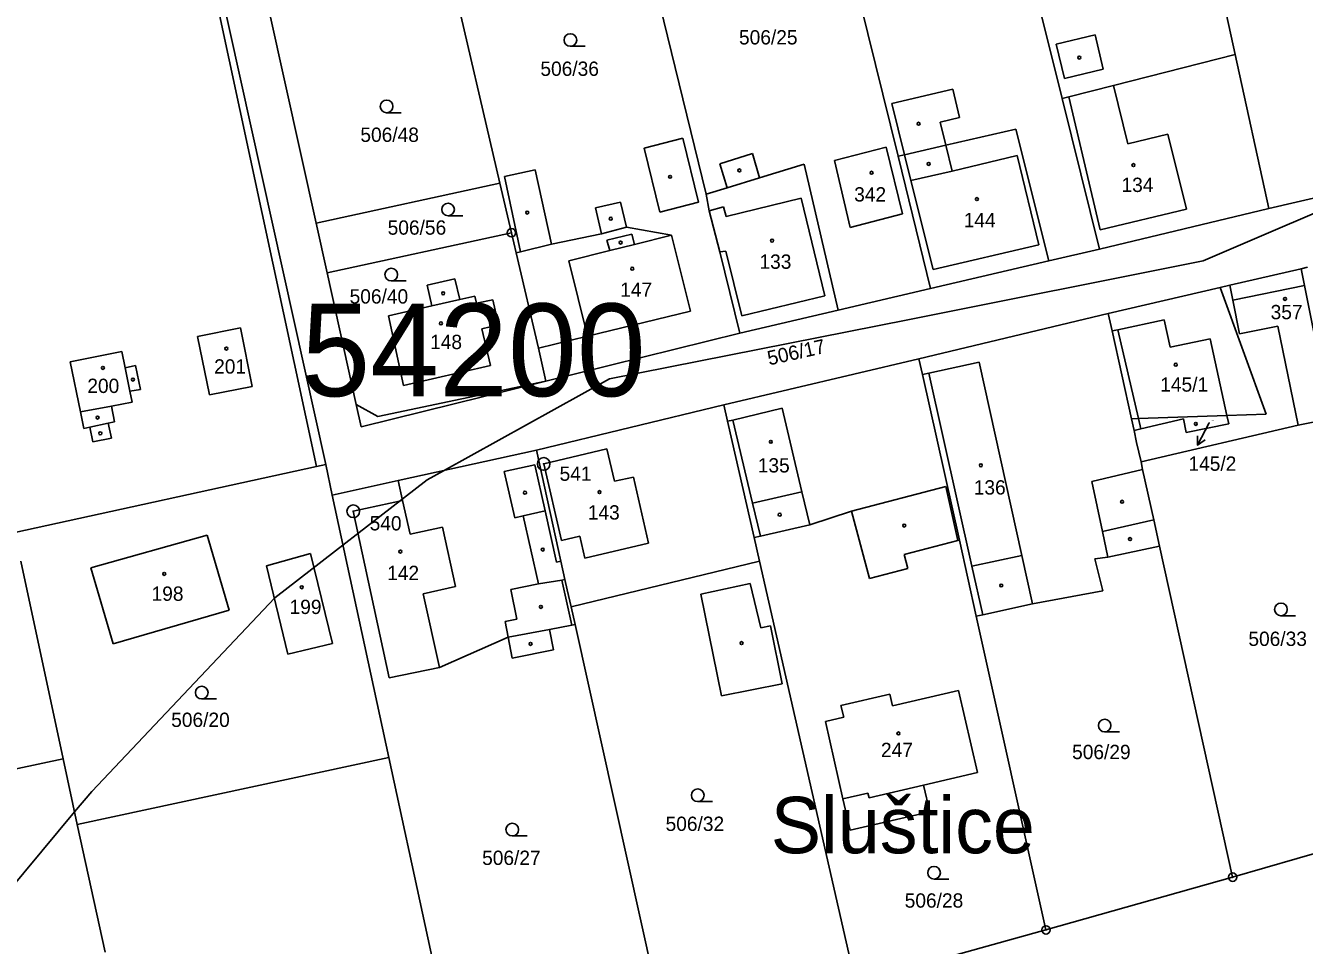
# Model space of a CAD drawing. Extents: x -725765 to -723182, y -1052705 to -1049154.
# Drawn here: x -724986 to -724834.1, y -1051317.3 to -1051208.1 of the extents above; entities that cross this region are included whole.
import ezdxf

# ---------------------------------------------------------------- set-up
doc = ezdxf.new("R2010")
doc.units = 0
for name, color, linetype in [('Vrstva 1', 7, 'Continuous'), ('Vrstva 15', 7, 'Continuous'), ('Vrstva 16', 7, 'Continuous'), ('Vrstva 17', 7, 'Continuous'), ('Vrstva 18', 7, 'Continuous'), ('Vrstva 19', 7, 'Continuous'), ('Vrstva 25', 7, 'Continuous'), ('Vrstva 4', 7, 'Continuous'), ('Vrstva 52', 7, 'Continuous'), ('Vrstva 53', 7, 'Continuous')]:
    doc.layers.add(name, color=color, linetype=linetype)

msp = doc.modelspace()

# ---------------------------------------------------------------- linework, layer by layer
at = {"layer": 'Vrstva 1'}
for points in [[(-724973.12, -1051157.17), (-724950.33, -1051260.17)], [(-724849.09, -1051180.48), (-724842.32, -1051211.51)], [(-724870.61, -1051185.73), (-724862.89, -1051216.71)], [(-724890.47, -1051190.71), (-724882.37, -1051223.57)], [(-724912.94, -1051196.18), (-724905.17, -1051228.09)], [(-724929.66, -1051226.78), (-724935.5, -1051201.73)], [(-724951.47, -1051231.54), (-724956.97, -1051206.71)], [(-724856.77, -1051215.16), (-724842.32, -1051211.51)], [(-724842.32, -1051211.51), (-724838.34, -1051229.79)], [(-724862.89, -1051216.71), (-724862.08, -1051216.5)], [(-724862.08, -1051216.5), (-724856.77, -1051215.16)], [(-724862.89, -1051216.71), (-724858.44, -1051234.59)], [(-724876.69, -1051222.27), (-724868.37, -1051220.37)], [(-724868.37, -1051220.37), (-724864.48, -1051236.01)], [(-724889.93, -1051224.09), (-724883.8, -1051222.5)], [(-724883.8, -1051222.5), (-724881.86, -1051230.43)], [(-724881.6, -1051223.39), (-724876.69, -1051222.27)], [(-724903.53, -1051224.49), (-724899.64, -1051223.26)], [(-724899.64, -1051223.26), (-724898.81, -1051226.13)], [(-724889.93, -1051224.09), (-724888.05, -1051232.02)], [(-724882.37, -1051223.57), (-724881.6, -1051223.39)], [(-724882.37, -1051223.57), (-724878.5, -1051239.3)], [(-724903.53, -1051224.49), (-724902.66, -1051227.32)], [(-724898.81, -1051226.13), (-724893.53, -1051224.5)], [(-724893.53, -1051224.5), (-724889.47, -1051241.86)], [(-724951.47, -1051231.54), (-724929.66, -1051226.78)], [(-724928.29, -1051232.66), (-724929.66, -1051226.78)], [(-724838.34, -1051229.79), (-724823.81, -1051226.41)], [(-724905.17, -1051228.09), (-724902.66, -1051227.32)], [(-724905.17, -1051228.09), (-724904.82, -1051230.05)], [(-724918.29, -1051229.71), (-724915.34, -1051229.02)], [(-724918.29, -1051229.71), (-724917.59, -1051232.77)], [(-724915.34, -1051229.02), (-724914.64, -1051232)], [(-724904.82, -1051230.05), (-724903.55, -1051234.94)], [(-724858.44, -1051234.59), (-724838.34, -1051229.79)], [(-724950.17, -1051237.43), (-724951.47, -1051231.54)], [(-724888.05, -1051232.02), (-724881.86, -1051230.43)], [(-724950.17, -1051237.43), (-724928.29, -1051232.66)], [(-724928.29, -1051232.66), (-724927.74, -1051235.04)], [(-724923.54, -1051234.03), (-724917.59, -1051232.77)], [(-724914.64, -1051232), (-724909.29, -1051232.93)], [(-724909.29, -1051232.93), (-724907.01, -1051241.97)], [(-724927.23, -1051234.92), (-724923.54, -1051234.03)], [(-724864.48, -1051236.01), (-724858.44, -1051234.59)], [(-724927.74, -1051235.04), (-724927.23, -1051234.92)], [(-724927.74, -1051235.04), (-724925.09, -1051246.38)], [(-724903.55, -1051234.94), (-724901.15, -1051244.59)], [(-724878.5, -1051239.3), (-724864.48, -1051236.01)], [(-724950.17, -1051237.43), (-724946.73, -1051253.05)], [(-724842.95, -1051238.88), (-724834.51, -1051236.93)], [(-724834.51, -1051236.93), (-724833.73, -1051236.75)], [(-724938.31, -1051238.87), (-724935.01, -1051238.12)], [(-724938.31, -1051238.87), (-724937.75, -1051241.35)], [(-724935.01, -1051238.12), (-724934.41, -1051240.6)], [(-724889.47, -1051241.86), (-724878.5, -1051239.3)], [(-724857.41, -1051242.23), (-724844.11, -1051239.15)], [(-724844.11, -1051239.15), (-724842.95, -1051238.88)], [(-724844.11, -1051239.15), (-724838.63, -1051254.19)], [(-724842.6, -1051240.67), (-724834.11, -1051238.93)], [(-724834.11, -1051238.93), (-724830.91, -1051254.72)], [(-724934.41, -1051240.6), (-724932.62, -1051240.19)], [(-724932.62, -1051240.19), (-724932.43, -1051241.04)], [(-724932.43, -1051241.04), (-724930.5, -1051240.61)], [(-724930.5, -1051240.61), (-724929.83, -1051243.59)], [(-724842.6, -1051240.67), (-724841.81, -1051244.68)], [(-724942.89, -1051242.52), (-724937.75, -1051241.35)], [(-724919.26, -1051244.96), (-724907.01, -1051241.97)], [(-724901.15, -1051244.59), (-724889.47, -1051241.86)], [(-724879.9, -1051247.64), (-724857.41, -1051242.23)], [(-724857.41, -1051242.23), (-724856.95, -1051244.32)], [(-724942.89, -1051242.52), (-724941.09, -1051250.79)], [(-724931.79, -1051244.06), (-724929.83, -1051243.59)], [(-724841.81, -1051244.68), (-724837.28, -1051243.75)], [(-724837.28, -1051243.75), (-724834.86, -1051255.5)], [(-724965.56, -1051244.97), (-724960.47, -1051243.94)], [(-724965.56, -1051244.97), (-724964.15, -1051251.92)], [(-724960.47, -1051243.94), (-724959.08, -1051250.93)], [(-724931.79, -1051244.06), (-724930.79, -1051248.41)], [(-724925.09, -1051246.38), (-724919.26, -1051244.96)], [(-724924.19, -1051250.27), (-724901.15, -1051244.59)], [(-724856.95, -1051244.32), (-724854.64, -1051254.76)], [(-724980.68, -1051247.97), (-724974.58, -1051246.75)], [(-724974.58, -1051246.75), (-724974.17, -1051248.71)], [(-724925.09, -1051246.38), (-724924.19, -1051250.27)], [(-724980.68, -1051247.97), (-724979.48, -1051253.94)], [(-724941.09, -1051250.79), (-724930.79, -1051248.41)], [(-724903.06, -1051253.09), (-724879.9, -1051247.64)], [(-724879.9, -1051247.64), (-724879.45, -1051249.51)], [(-724974.17, -1051248.71), (-724972.93, -1051248.44)], [(-724972.93, -1051248.44), (-724972.35, -1051251.27)], [(-724879.45, -1051249.51), (-724875.09, -1051269.17)], [(-724973.6, -1051251.47), (-724972.35, -1051251.27)], [(-724964.15, -1051251.92), (-724959.08, -1051250.93)], [(-724946.15, -1051255.69), (-724924.19, -1051250.27)], [(-724975.8, -1051253.25), (-724973.33, -1051252.78)], [(-724973.6, -1051251.47), (-724973.33, -1051252.78)], [(-724979.48, -1051253.94), (-724979.09, -1051255.9)], [(-724975.8, -1051253.25), (-724975.43, -1051255.13)], [(-724946.73, -1051253.05), (-724946.15, -1051255.69)], [(-724925.3, -1051258.49), (-724903.06, -1051253.09)], [(-724903.06, -1051253.09), (-724902.62, -1051255.04)], [(-724853.82, -1051254.73), (-724843.31, -1051254.36)], [(-724843.31, -1051254.36), (-724838.63, -1051254.19)], [(-724843.31, -1051254.36), (-724843.09, -1051255.35)], [(-724979.09, -1051255.9), (-724978.35, -1051255.75)], [(-724978.35, -1051255.75), (-724977.99, -1051257.49)], [(-724976.2, -1051255.29), (-724975.43, -1051255.13)], [(-724976.2, -1051255.29), (-724975.78, -1051257.06)], [(-724902.62, -1051255.04), (-724899.47, -1051268.86)], [(-724854.64, -1051254.76), (-724853.82, -1051254.73)], [(-724854.64, -1051254.76), (-724854.34, -1051256.14)], [(-724853.82, -1051254.73), (-724853.54, -1051255.95)], [(-724853.54, -1051255.95), (-724848.46, -1051254.77)], [(-724848.46, -1051254.77), (-724848.14, -1051256.37)], [(-724848.14, -1051256.37), (-724843.09, -1051255.35)], [(-724834.86, -1051255.5), (-724830.91, -1051254.72)], [(-724977.99, -1051257.49), (-724975.78, -1051257.06)], [(-724854.34, -1051256.14), (-724854.03, -1051257.56)], [(-724941.73, -1051262.1), (-724925.3, -1051258.49)], [(-724925.3, -1051258.49), (-724922.43, -1051271.66)], [(-724854.03, -1051257.56), (-724853.51, -1051259.87)], [(-724987.27, -1051268.24), (-724951.45, -1051260.42)], [(-724951.45, -1051260.42), (-724950.33, -1051260.17)], [(-724950.33, -1051260.17), (-724949.59, -1051263.83)], [(-724853.51, -1051259.87), (-724853.32, -1051260.77)], [(-724853.32, -1051260.77), (-724852, -1051266.76)], [(-724949.59, -1051263.83), (-724941.73, -1051262.1)], [(-724941.73, -1051262.1), (-724941.21, -1051264.44)], [(-724949.59, -1051263.83), (-724942.84, -1051294.98)], [(-724947.08, -1051265.73), (-724941.21, -1051264.44)], [(-724947.08, -1051265.73), (-724942.8, -1051285.51)], [(-724892.83, -1051267.33), (-724887.9, -1051265.73)], [(-724887.9, -1051265.73), (-724885.76, -1051273.72)], [(-724898.72, -1051268.69), (-724892.83, -1051267.33)], [(-724852, -1051266.76), (-724851.31, -1051269.88)], [(-724978.23, -1051272.46), (-724964.44, -1051268.56)], [(-724964.44, -1051268.56), (-724961.82, -1051277.49)], [(-724899.47, -1051268.86), (-724898.72, -1051268.69)], [(-724899.47, -1051268.86), (-724898.83, -1051271.67)], [(-724881.65, -1051270.87), (-724875.25, -1051269.21)], [(-724875.25, -1051269.21), (-724875.09, -1051269.17)], [(-724875.09, -1051269.17), (-724873.08, -1051278.19)], [(-724957.39, -1051272.21), (-724952.16, -1051270.77)], [(-724952.16, -1051270.77), (-724949.53, -1051281.43)], [(-724881.65, -1051270.87), (-724881.21, -1051272.55)], [(-724859.01, -1051271.39), (-724857.44, -1051271.18)], [(-724857.44, -1051271.18), (-724851.31, -1051269.88)], [(-724851.31, -1051269.88), (-724842.63, -1051309.19)], [(-724986.54, -1051271.66), (-724981.52, -1051295.13)], [(-724978.23, -1051272.46), (-724975.58, -1051281.47)], [(-724957.39, -1051272.21), (-724954.83, -1051282.72)], [(-724922.43, -1051271.66), (-724921.95, -1051273.85)], [(-724921.18, -1051277.09), (-724898.83, -1051271.67)], [(-724898.83, -1051271.67), (-724887.44, -1051321.75)], [(-724885.76, -1051273.72), (-724881.21, -1051272.55)], [(-724859.01, -1051271.39), (-724858.06, -1051275.2)], [(-724921.95, -1051273.85), (-724921.68, -1051275.08)], [(-724921.68, -1051275.08), (-724921.18, -1051277.09)], [(-724866.41, -1051276.72), (-724858.06, -1051275.2)], [(-724921.18, -1051277.09), (-724920.71, -1051279.19)], [(-724872.3, -1051278.02), (-724866.41, -1051276.72)], [(-724975.58, -1051281.47), (-724961.82, -1051277.49)], [(-724873.08, -1051278.19), (-724872.3, -1051278.02)], [(-724873.08, -1051278.19), (-724864.8, -1051315.46)], [(-724928.67, -1051280.7), (-724923.77, -1051279.79)], [(-724923.77, -1051279.79), (-724921.11, -1051279.27)], [(-724921.11, -1051279.27), (-724920.71, -1051279.19)], [(-724920.71, -1051279.19), (-724909.84, -1051328.29)], [(-724954.83, -1051282.72), (-724949.53, -1051281.43)], [(-724936.83, -1051284.28), (-724928.67, -1051280.7)], [(-724942.8, -1051285.51), (-724936.83, -1051284.28)], [(-724889.15, -1051288.79), (-724883.34, -1051287.46)], [(-724883.34, -1051287.46), (-724883.02, -1051288.86)], [(-724883.02, -1051288.86), (-724875.19, -1051287.04)], [(-724875.19, -1051287.04), (-724872.93, -1051296.76)], [(-724889.15, -1051288.79), (-724888.81, -1051290.2)], [(-724890.99, -1051290.71), (-724888.81, -1051290.2)], [(-724890.99, -1051290.71), (-724888.91, -1051299.9)], [(-725024.07, -1051304.22), (-724981.52, -1051295.13)], [(-724981.52, -1051295.13), (-724979.85, -1051302.94)], [(-724979.85, -1051302.94), (-724942.84, -1051294.98)], [(-724942.84, -1051294.98), (-724934.23, -1051334.87)], [(-724879.34, -1051298.26), (-724872.93, -1051296.76)], [(-724879.34, -1051298.26), (-724878.59, -1051301.45)], [(-724888.91, -1051299.9), (-724888.07, -1051303.62)], [(-724888.07, -1051303.62), (-724878.59, -1051301.45)], [(-724979.85, -1051302.94), (-724976.54, -1051318.1)], [(-724842.63, -1051309.19), (-724819.59, -1051302.54)], [(-724864.8, -1051315.46), (-724842.63, -1051309.19)], [(-724887.44, -1051321.75), (-724864.8, -1051315.46)]]:
    msp.add_lwpolyline(points, dxfattribs=at)
at = {"layer": 'Vrstva 16'}
msp.add_lwpolyline([(-724845.39, -1051255.22), (-724845.4, -1051255.24)], dxfattribs=at)
at = {"layer": 'Vrstva 25'}
for points in [[(-724921.29, -1051210.52), (-724919.54, -1051210.52)], [(-724943.12, -1051218.41), (-724941.37, -1051218.41)], [(-724935.82, -1051230.65), (-724934.07, -1051230.65)], [(-724942.56, -1051238.38), (-724940.81, -1051238.38)], [(-724845.4, -1051255.24), (-724846.82, -1051257.88)], [(-724845.91, -1051257.24), (-724846.82, -1051257.88), (-724846.79, -1051256.76)], [(-724836.9, -1051278.14), (-724835.15, -1051278.14)], [(-724965.07, -1051288.02), (-724963.32, -1051288.02)], [(-724857.83, -1051291.93), (-724856.08, -1051291.93)], [(-724906.16, -1051300.21), (-724904.41, -1051300.21)], [(-724928.19, -1051304.29), (-724926.44, -1051304.29)], [(-724878.09, -1051309.42), (-724876.34, -1051309.42)]]:
    msp.add_lwpolyline(points, dxfattribs=at)
for centre, radius in [((-724921.29, -1051209.77), 0.75), ((-724860.84, -1051211.86), 0.175), ((-724943.12, -1051217.66), 0.75), ((-724879.93, -1051219.72), 0.175), ((-724901.22, -1051225.26), 0.175), ((-724885.52, -1051225.54), 0.175), ((-724878.73, -1051224.48), 0.175), ((-724854.41, -1051224.62), 0.175), ((-724909.45, -1051226.02), 0.175), ((-724873, -1051228.66), 0.175), ((-724935.82, -1051229.9), 0.75), ((-724926.41, -1051230.26), 0.175), ((-724916.49, -1051230.99), 0.175), ((-724928.29, -1051232.66), 0.5), ((-724928.29, -1051232.66), 0.032), ((-724915.32, -1051233.83), 0.175), ((-724897.33, -1051233.6), 0.175), ((-724942.56, -1051237.63), 0.75), ((-724913.94, -1051236.93), 0.175), ((-724936.4, -1051239.85), 0.175), ((-724836.41, -1051240.52), 0.175), ((-724936.66, -1051243.42), 0.175), ((-724962.15, -1051246.41), 0.175), ((-724849.39, -1051248.33), 0.175), ((-724976.81, -1051248.71), 0.175), ((-724973.25, -1051250.1), 0.175), ((-724977.44, -1051254.61), 0.175), ((-724847, -1051255.36), 0.175), ((-724977.12, -1051256.48), 0.175), ((-724897.48, -1051257.49), 0.175), ((-724924.46, -1051260.11), 0.75), ((-724924.46, -1051260.11), 0.032), ((-724872.54, -1051260.28), 0.175), ((-724926.68, -1051263.53), 0.175), ((-724917.83, -1051263.46), 0.175), ((-724947.08, -1051265.73), 0.75), ((-724855.76, -1051264.61), 0.175), ((-724947.08, -1051265.73), 0.032), ((-724896.43, -1051266.14), 0.175), ((-724881.64, -1051267.44), 0.175), ((-724854.82, -1051269.04), 0.175), ((-724941.48, -1051270.52), 0.175), ((-724924.57, -1051270.28), 0.175), ((-724969.52, -1051273.17), 0.175), ((-724953.19, -1051274.76), 0.175), ((-724870.11, -1051274.55), 0.175), ((-724924.79, -1051277.09), 0.175), ((-724836.9, -1051277.39), 0.75), ((-724926.02, -1051281.49), 0.175), ((-724900.96, -1051281.39), 0.175), ((-724965.07, -1051287.27), 0.75), ((-724857.83, -1051291.18), 0.75), ((-724882.32, -1051292.12), 0.175), ((-724906.16, -1051299.46), 0.75), ((-724928.19, -1051303.54), 0.75), ((-724878.09, -1051308.67), 0.75), ((-724842.63, -1051309.19), 0.5), ((-724842.63, -1051309.19), 0.032), ((-724864.8, -1051315.46), 0.5), ((-724864.8, -1051315.46), 0.032)]:
    msp.add_circle(centre, radius, dxfattribs=at)
at = {"layer": 'Vrstva 4'}
for points in [[(-724973.59, -1051157.32), (-724951.45, -1051260.42)], [(-724863.59, -1051210.27), (-724858.97, -1051209.17)], [(-724863.59, -1051210.27), (-724862.62, -1051214.34)], [(-724858.97, -1051209.17), (-724858, -1051213.24)], [(-724862.62, -1051214.34), (-724858, -1051213.24)], [(-724883.1, -1051217.33), (-724875.88, -1051215.6)], [(-724875.88, -1051215.6), (-724875.07, -1051218.97)], [(-724862.08, -1051216.5), (-724858.35, -1051232.31)], [(-724856.77, -1051215.16), (-724855.07, -1051222.12)], [(-724883.1, -1051217.33), (-724881.6, -1051223.39)], [(-724877.36, -1051219.54), (-724875.07, -1051218.97)], [(-724877.36, -1051219.54), (-724876.69, -1051222.27)], [(-724855.07, -1051222.12), (-724850.31, -1051220.94)], [(-724850.31, -1051220.94), (-724848.1, -1051229.85)], [(-724912.53, -1051222.63), (-724907.92, -1051221.43)], [(-724907.92, -1051221.43), (-724906.06, -1051229.01)], [(-724876.69, -1051222.27), (-724875.93, -1051225.35)], [(-724912.53, -1051222.63), (-724910.68, -1051230.22)], [(-724881.6, -1051223.39), (-724880.84, -1051226.45)], [(-724875.93, -1051225.35), (-724868.22, -1051223.49)], [(-724868.22, -1051223.49), (-724865.66, -1051234.08)], [(-724929.13, -1051225.97), (-724925.47, -1051225.17)], [(-724925.47, -1051225.17), (-724923.54, -1051234.03)], [(-724880.84, -1051226.45), (-724875.93, -1051225.35)], [(-724929.13, -1051225.97), (-724927.23, -1051234.92)], [(-724902.66, -1051227.32), (-724898.81, -1051226.13)], [(-724880.84, -1051226.45), (-724878.21, -1051237.03)], [(-724902.8, -1051230.73), (-724893.88, -1051228.57)], [(-724893.88, -1051228.57), (-724891.08, -1051240.14)], [(-724910.68, -1051230.22), (-724906.06, -1051229.01)], [(-724904.82, -1051230.05), (-724903.1, -1051229.57)], [(-724903.1, -1051229.57), (-724902.8, -1051230.73)], [(-724858.35, -1051232.31), (-724848.1, -1051229.85)], [(-724917.59, -1051232.77), (-724914.64, -1051232)], [(-724916.94, -1051233.55), (-724914, -1051232.81)], [(-724914, -1051232.81), (-724913.69, -1051234.04)], [(-724913.69, -1051234.04), (-724909.29, -1051232.93)], [(-724916.94, -1051233.55), (-724916.61, -1051234.77)], [(-724916.61, -1051234.77), (-724913.69, -1051234.04)], [(-724878.21, -1051237.03), (-724865.66, -1051234.08)], [(-724921.48, -1051236), (-724916.61, -1051234.77)], [(-724921.48, -1051236), (-724919.26, -1051244.96)], [(-724903.55, -1051234.94), (-724902.83, -1051234.84)], [(-724902.83, -1051234.84), (-724900.91, -1051242.51)], [(-724834.51, -1051236.93), (-724834.11, -1051238.93)], [(-724842.95, -1051238.88), (-724842.6, -1051240.67)], [(-724937.75, -1051241.35), (-724934.41, -1051240.6)], [(-724900.91, -1051242.51), (-724891.08, -1051240.14)], [(-724856.27, -1051244.18), (-724850.77, -1051243.01)], [(-724850.77, -1051243.01), (-724850.06, -1051246.23)], [(-724856.95, -1051244.32), (-724856.27, -1051244.18)], [(-724856.27, -1051244.18), (-724853.82, -1051254.73)], [(-724850.06, -1051246.23), (-724845.31, -1051245.26)], [(-724845.31, -1051245.26), (-724843.31, -1051254.36)], [(-724878.72, -1051249.35), (-724872.74, -1051248.01)], [(-724872.74, -1051248.01), (-724867.67, -1051270.99)], [(-724974.17, -1051248.71), (-724973.6, -1051251.47)], [(-724879.45, -1051249.51), (-724878.72, -1051249.35)], [(-724878.72, -1051249.35), (-724873.59, -1051272.27)], [(-724944.15, -1051254.48), (-724924.19, -1051250.27)], [(-724979.48, -1051253.94), (-724975.8, -1051253.25)], [(-724946.73, -1051253.05), (-724944.15, -1051254.48)], [(-724902.01, -1051254.9), (-724896.12, -1051253.5)], [(-724896.12, -1051253.5), (-724893.78, -1051263.41)], [(-724978.35, -1051255.75), (-724976.2, -1051255.29)], [(-724902.62, -1051255.04), (-724902.01, -1051254.9)], [(-724902.01, -1051254.9), (-724899.66, -1051264.76)], [(-724854.34, -1051256.14), (-724853.54, -1051255.95)], [(-724853.51, -1051259.87), (-724834.86, -1051255.5)], [(-724924.46, -1051260.11), (-724916.96, -1051258.32)], [(-724916.96, -1051258.32), (-724916.04, -1051262.16)], [(-724929.15, -1051261), (-724925.5, -1051260.24)], [(-724925.5, -1051260.24), (-724924.28, -1051265.69)], [(-724924.46, -1051260.11), (-724922.35, -1051269.19)], [(-724929.15, -1051261), (-724927.9, -1051266.51)], [(-724916.04, -1051262.16), (-724913.81, -1051261.7)], [(-724913.81, -1051261.7), (-724912, -1051269.54)], [(-724859.36, -1051262.2), (-724853.32, -1051260.77)], [(-724899.66, -1051264.76), (-724893.78, -1051263.41)], [(-724893.78, -1051263.41), (-724892.83, -1051267.33)], [(-724887.9, -1051265.73), (-724876.7, -1051262.79)], [(-724876.7, -1051262.79), (-724875.25, -1051269.21)], [(-724859.36, -1051262.2), (-724858.09, -1051268.14)], [(-724941.21, -1051264.44), (-724940.31, -1051268.46)], [(-724899.66, -1051264.76), (-724898.72, -1051268.69)], [(-724927.9, -1051266.51), (-724926.89, -1051266.28)], [(-724926.89, -1051266.28), (-724924.28, -1051265.69)], [(-724926.89, -1051266.28), (-724925.07, -1051274.36)], [(-724924.28, -1051265.69), (-724922.94, -1051271.78)], [(-724940.31, -1051268.46), (-724936.48, -1051267.64)], [(-724936.48, -1051267.64), (-724934.92, -1051274.68)], [(-724858.09, -1051268.14), (-724852, -1051266.76)], [(-724858.09, -1051268.14), (-724857.44, -1051271.18)], [(-724922.35, -1051269.19), (-724920.15, -1051268.7)], [(-724920.15, -1051268.7), (-724919.56, -1051271.32)], [(-724919.56, -1051271.32), (-724912, -1051269.54)], [(-724873.59, -1051272.27), (-724867.67, -1051270.99)], [(-724867.67, -1051270.99), (-724866.41, -1051276.72)], [(-724922.94, -1051271.78), (-724922.43, -1051271.66)], [(-724873.59, -1051272.27), (-724872.3, -1051278.02)], [(-724925.07, -1051274.36), (-724922.29, -1051273.92)], [(-724922.29, -1051273.92), (-724921.95, -1051273.85)], [(-724922.29, -1051273.92), (-724921.11, -1051279.27)], [(-724938.76, -1051275.54), (-724934.92, -1051274.68)], [(-724938.76, -1051275.54), (-724936.83, -1051284.28)], [(-724928.37, -1051275.03), (-724925.07, -1051274.36)], [(-724928.37, -1051275.03), (-724927.65, -1051278.56)], [(-724905.81, -1051275.58), (-724899.94, -1051274.31)], [(-724905.81, -1051275.58), (-724903.32, -1051287.66)], [(-724899.94, -1051274.31), (-724898.65, -1051279.57)], [(-724929.02, -1051278.83), (-724927.65, -1051278.56)], [(-724929.02, -1051278.83), (-724928.67, -1051280.7)], [(-724923.77, -1051279.79), (-724923.29, -1051282.21)], [(-724898.65, -1051279.57), (-724897.52, -1051279.34)], [(-724897.52, -1051279.34), (-724896.14, -1051286.21)], [(-724928.67, -1051280.7), (-724928.21, -1051283.2)], [(-724928.21, -1051283.2), (-724923.29, -1051282.21)], [(-724903.32, -1051287.66), (-724896.14, -1051286.21)], [(-724885.82, -1051299.77), (-724879.34, -1051298.26)], [(-724888.91, -1051299.9), (-724885.96, -1051299.23)], [(-724885.96, -1051299.23), (-724885.82, -1051299.77)]]:
    msp.add_lwpolyline(points, dxfattribs=at)
at = {"layer": 'Vrstva 52'}
msp.add_lwpolyline([(-724758.63, -1051111), (-724749.19, -1051116), (-724741.88, -1051126), (-724736.88, -1051142), (-724736.13, -1051150), (-724741.19, -1051160), (-724749.88, -1051170), (-724773.81, -1051191), (-724798.38, -1051209), (-724824.48, -1051226.57), (-724825.13, -1051227), (-724846.13, -1051236), (-724881.19, -1051243), (-724916.63, -1051250), (-724936.36, -1051260.92), (-724938.31, -1051262), (-724956.38, -1051276), (-724978.13, -1051299), (-724980.17, -1051301.45), (-725000, -1051325.25)], dxfattribs=at)

# ---------------------------------------------------------------- texts
at = {"layer": 'Vrstva 15'}
msp.add_text('Sluštice', height=6.7, dxfattribs=at).set_placement((-724897.49, -1051306.35))
at = {"layer": 'Vrstva 16'}
msp.add_text('145/2', height=1.7, dxfattribs=at).set_placement((-724847.88, -1051260.93))
at = {"layer": 'Vrstva 17'}
for s, p in [('541', (-724922.57, -1051262.12)), ('540', (-724945.13, -1051268.01))]:
    msp.add_text(s, height=1.7, dxfattribs=at).set_placement(p)
at = {"layer": 'Vrstva 18'}
for s, p in [('506/25', (-724901.26, -1051210.3)), ('506/36', (-724924.85, -1051214.03)), ('506/48', (-724946.23, -1051221.87)), ('506/56', (-724942.99, -1051232.89)), ('506/40', (-724947.51, -1051241.07)), ('506/33', (-724840.76, -1051281.73)), ('506/20', (-724968.7, -1051291.35)), ('506/29', (-724861.7, -1051295.17)), ('506/32', (-724909.98, -1051303.7)), ('506/27', (-724931.77, -1051307.74)), ('506/28', (-724881.58, -1051312.81))]:
    msp.add_text(s, height=1.7, dxfattribs=at).set_placement(p)
msp.add_text('506/17', height=1.7, rotation=12.5001, dxfattribs=at).set_placement((-724897.68, -1051248.42))
at = {"layer": 'Vrstva 19'}
for s, height, p in [('134', 1.7, (-724855.83, -1051227.82)), ('342', 1.7, (-724887.58, -1051228.95)), ('144', 1.7, (-724874.57, -1051232)), ('133', 1.7, (-724898.83, -1051236.94)), ('147', 1.7, (-724915.37, -1051240.27)), ('357', 1.7, (-724838.12, -1051242.93)), ('148', 1.7, (-724937.95, -1051246.48)), ('201', 1.7, (-724963.6, -1051249.39)), ('145/1', 1.7, (-724851.23, -1051251.53)), ('200', 1.7, (-724978.66, -1051251.69)), ('145/2', 0.1, (-724845.19, -1051255.02)), ('135', 1.7, (-724899.03, -1051261.13)), ('136', 1.7, (-724873.38, -1051263.75)), ('143', 1.7, (-724919.22, -1051266.72)), ('142', 1.7, (-724943.05, -1051273.91)), ('198', 1.7, (-724971.03, -1051276.37)), ('199', 1.7, (-724954.64, -1051277.94)), ('247', 1.7, (-724884.4, -1051294.93))]:
    msp.add_text(s, height=height, dxfattribs=at).set_placement(p)
at = {"layer": 'Vrstva 53'}
msp.add_text('54200', height=11, dxfattribs=at).set_placement((-724953.24, -1051252.07))

doc.saveas('drawing.dxf')
